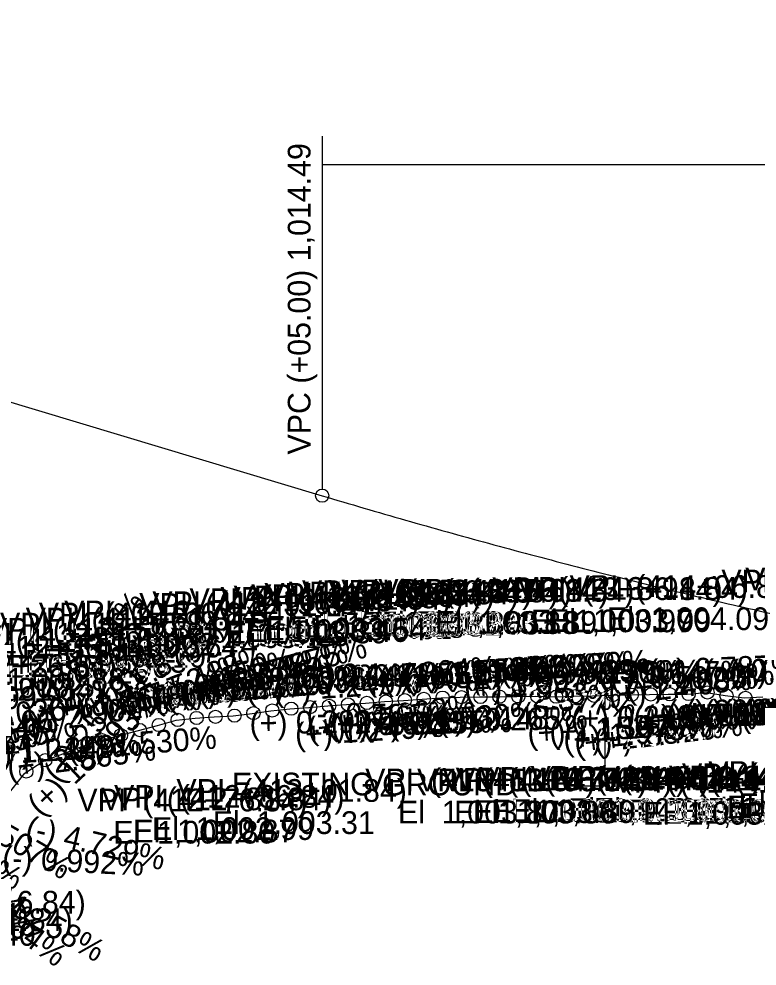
# Model space of a CAD drawing. Extents: x 150 to 16976893, y 3102 to 12559827.
# Drawn here: x 16975617.8 to 16975812.8, y 12558887.5 to 12559137.8 of the extents above; entities that cross this region are included whole.
import ezdxf

# ---------------------------------------------------------------- set-up
doc = ezdxf.new("R2010")
doc.units = 0
for name, color, linetype in [('RD_DDB_Ex_Tx', 7, 'Continuous'), ('RD_DDB_GradeTX', 7, 'Continuous'), ('RD_DDB_PI', 7, 'Continuous'), ('RD_DDB_Profile_EX', 7, 'Continuous'), ('RD_HC_TX_Sta20', 7, 'Continuous'), ('RD_XS_Misc_Line', 7, 'Continuous')]:
    doc.layers.add(name, color=color, linetype=linetype)

msp = doc.modelspace()

# ---------------------------------------------------------------- linework, layer by layer
at = {"layer": 'RD_DDB_Ex_Tx'}
for p, q in [((16975772.67, 12558935.06), (16975772.67, 12558958.98)), ((16975762.95, 12558935.06), (16975772.67, 12558935.06))]:
    msp.add_line(p, q, dxfattribs=at)
at = {"layer": 'RD_DDB_PI'}
for centre in [(16975729.74, 12558958.39), (16975734.74, 12558958.51), (16975739.74, 12558958.58), (16975744.74, 12558958.65), (16975749.74, 12558958.73), (16975754.74, 12558958.76), (16975759.74, 12558958.64), (16975764.74, 12558958.76), (16975769.74, 12558958.9), (16975774.74, 12558959.04), (16975779.74, 12558959.18), (16975784.74, 12558959.25), (16975789.74, 12558959.29), (16975794.74, 12558959.35), (16975799.74, 12558959.75), (16975804.74, 12558958.91), (16975699.74, 12558956.24), (16975704.74, 12558956.62), (16975709.74, 12558957), (16975714.74, 12558957.37), (16975719.74, 12558957.71), (16975724.74, 12558958.05), (16975809.74, 12558958.32), (16975674.74, 12558953.64), (16975679.74, 12558954.28), (16975684.74, 12558955.01), (16975689.74, 12558955.47), (16975694.74, 12558955.86), (16975654.74, 12558951.16), (16975659.74, 12558952.51), (16975664.74, 12558953.02), (16975669.74, 12558953.33), (16975644.74, 12558948.48), (16975649.74, 12558949.82), (16975639.74, 12558947.13), (16975629.74, 12558943.72), (16975634.74, 12558945.59), (16975624.74, 12558941.84), (16975619.74, 12558938.87)]:
    msp.add_circle(centre, 1.75, dxfattribs=at)
at = {"layer": 'RD_DDB_Profile_EX'}
for points in [[(16975614.37, 12558932.13), (16975619.37, 12558938.41), (16975624.37, 12558941.7), (16975629.37, 12558943.58), (16975634.37, 12558945.45), (16975639.37, 12558947.03), (16975644.37, 12558948.38), (16975649.37, 12558949.72), (16975654.37, 12558951.06), (16975659.37, 12558952.41), (16975664.37, 12558952.99), (16975669.37, 12558953.3), (16975674.37, 12558953.62), (16975679.37, 12558954.23), (16975684.37, 12558954.95), (16975689.37, 12558955.44), (16975694.37, 12558955.83), (16975699.37, 12558956.21), (16975704.37, 12558956.59), (16975709.37, 12558956.97), (16975714.37, 12558957.34), (16975719.37, 12558957.68), (16975724.37, 12558958.03), (16975729.37, 12558958.37), (16975734.37, 12558958.5), (16975739.37, 12558958.58), (16975744.37, 12558958.65), (16975749.37, 12558958.72), (16975754.37, 12558958.79), (16975759.37, 12558958.63)], [(16975759.37, 12558958.63), (16975764.37, 12558958.76), (16975769.37, 12558958.89), (16975774.37, 12558959.03), (16975779.37, 12558959.17), (16975784.37, 12558959.25), (16975789.37, 12558959.28), (16975794.37, 12558959.32), (16975799.37, 12558959.72), (16975804.37, 12558958.98), (16975809.37, 12558958.3), (16975814.37, 12558958.58)]]:
    msp.add_lwpolyline(points, dxfattribs=at)
at = {"layer": 'RD_HC_TX_Sta20'}
for p, q in [((16975697.9, 12559106.77), (16975697.9, 12559013.52)), ((16975697.9, 12559099.27), (16976247.9, 12559099.27))]:
    msp.add_line(p, q, dxfattribs=at)
msp.add_circle((16975697.9, 12559011.77), 1.75, dxfattribs=at)
at = {"layer": 'RD_XS_Misc_Line'}
msp.add_line((16975277.9, 12559137.77), (16975697.9, 12559011.77), dxfattribs=at)
msp.add_spline([(16975697.9, 12559011.77), (16975708.9, 12559008.5), (16975719.9, 12559005.32), (16975730.9, 12559002.21), (16975741.9, 12558999.18), (16975752.9, 12558996.22), (16975763.9, 12558993.34), (16975774.9, 12558990.54), (16975785.9, 12558987.81), (16975796.9, 12558985.16), (16975807.9, 12558982.59), (16975818.9, 12558980.09), (16975829.9, 12558977.67), (16975840.9, 12558975.33), (16975851.9, 12558973.06), (16975862.9, 12558970.87), (16975873.9, 12558968.76), (16975884.9, 12558966.72), (16975895.9, 12558964.76), (16975906.9, 12558962.87), (16975917.9, 12558961.06), (16975928.9, 12558959.33), (16975939.9, 12558957.67), (16975950.9, 12558956.09), (16975961.9, 12558954.59), (16975972.9, 12558953.17), (16975983.9, 12558951.82), (16975994.9, 12558950.54), (16976005.9, 12558949.35), (16976016.9, 12558948.23), (16976027.9, 12558947.18), (16976038.9, 12558946.21), (16976049.9, 12558945.32), (16976060.9, 12558944.51), (16976071.9, 12558943.77), (16976082.9, 12558943.11), (16976093.9, 12558942.52), (16976104.9, 12558942.02), (16976115.9, 12558941.58), (16976126.9, 12558941.23), (16976137.9, 12558940.95), (16976148.9, 12558940.75), (16976159.9, 12558940.62), (16976170.9, 12558940.57), (16976181.9, 12558940.6), (16976192.9, 12558940.7), (16976203.9, 12558940.88), (16976214.9, 12558941.14), (16976225.9, 12558941.47), (16976236.9, 12558941.88), (16976247.9, 12558942.36)], degree=3, dxfattribs=at)

# ---------------------------------------------------------------- texts
at = {"layer": 'RD_DDB_Ex_Tx'}
msp.add_text('EXISTING GROUND', height=6, dxfattribs=at).set_placement((16975674.08, 12558932.56))
at = {"layer": 'RD_DDB_GradeTX'}
for s, rotation, p in [('(+) 25.101%', 51.4525, (16975624.12, 12558949.19)), ('(+) 11.870%', 30.6881, (16975634.95, 12558951.39)), ('(+) 5.375%', 15.0437, (16975667.08, 12558957.59)), ('(+) 5.375%', 15.0437, (16975672.08, 12558958.93)), ('(+) 25.101%', 51.4525, (16975628.51, 12558935.43)), ('(+) 7.524%', 20.6166, (16975641.52, 12558951.36)), ('(+) 7.488%', 20.5259, (16975646.87, 12558953.34)), ('(+) 6.150%', 17.092, (16975653.6, 12558954.53)), ('(+) 5.375%', 15.0437, (16975657.08, 12558954.9)), ('(+) 5.375%', 15.0437, (16975662.08, 12558956.24)), ('(+) 1.450%', 4.1457, (16975730.12, 12558961.49)), ('(+) 1.370%', 3.9181, (16975735.14, 12558961.77)), ('(+) 1.370%', 3.9181, (16975740.14, 12558962.11)), ('(+) 1.370%', 3.9181, (16975745.14, 12558962.45)), ('(+) 0.147%', 0.4204, (16975690.78, 12558961.29)), ('(+) 1.864%', 5.3242, (16975705.26, 12558959.93)), ('(+) 1.530%', 4.3757, (16975709.69, 12558960.01)), ('(+) 0.274%', 0.7847, (16975718.88, 12558961.35)), ('(+) 1.530%', 4.3757, (16975719.69, 12558960.77)), ('(+) 1.530%', 4.3757, (16975724.69, 12558961.16)), ('(+) 0.463%', 1.3272, (16975748.6, 12558961.83)), ('(+) 0.290%', 0.8315, (16975753.57, 12558961.78)), ('(+) 0.290%', 0.8315, (16975758.57, 12558961.86)), ('(+) 0.147%', 0.4204, (16975770.78, 12558961.88)), ('(+) 2.093%', 5.9736, (16975778.37, 12558957.81)), ('(+) 0.787%', 2.2534, (16975784.26, 12558962.36)), ('(+) 0.274%', 0.7847, (16975798.87, 12558962.44)), ('(+) 0.148%', 0.4231, (16975805.49, 12558962.4)), ('(+) 1.370%', 3.9181, (16975660.34, 12558956.65)), ('(+) 1.370%', 3.9181, (16975665.34, 12558956.99)), ('(+) 0.463%', 1.3272, (16975668.63, 12558959.98)), ('(+) 0.290%', 0.8315, (16975673.58, 12558960.62)), ('(+) 2.036%', 5.813, (16975677.92, 12558957.37)), ('(+) 0.290%', 0.8317, (16975683.58, 12558960.77)), ('(+) 1.249%', 3.5746, (16975685.16, 12558957.3)), ('(+) 0.577%', 1.6513, (16975714.15, 12558960.29)), ('(+) 1.597%', 4.5659, (16975735.65, 12558957.64)), ('(-) 3.363%', 350.4538, (16975737.4, 12558961.11)), ('(+) 2.468%', 7.0355, (16975773.87, 12558956.11)), ('(-) 0.507%', 358.5486, (16975773.98, 12558961.28)), ('(+) 1.530%', 4.3757, (16975634.94, 12558954.29)), ('(+) 1.530%', 4.3757, (16975639.94, 12558954.67)), ('(+) 1.530%', 4.3757, (16975644.94, 12558955.05)), ('(+) 1.450%', 4.1457, (16975650.34, 12558955.71)), ('(+) 1.370%', 3.9181, (16975655.34, 12558956.3)), ('(-) 2.377%', 353.2234, (16975743.2, 12558957.16)), ('(+) 18.593%', 42.912, (16975623.48, 12558926.81)), ('(+) 1.864%', 5.3242, (16975625.63, 12558952.51)), ('(+) 2.036%', 5.813, (16975598.36, 12558949.27)), ('(+) 2.902%', 8.255, (16975618.64, 12558948.45)), ('(+) 2.565%', 7.3071, (16975694.38, 12558947.08)), ('(+) 2.902%', 8.255, (16975699.48, 12558948.05)), ('(+) 0.460%', 1.317, (16975789.2, 12558951.54)), ('(+) 0.482%', 1.3806, (16975793.86, 12558951.58)), ('(+) 0.577%', 1.6513, (16975794.46, 12558950.6)), ('(+) 0.504%', 1.4441, (16975798.99, 12558951.64)), ('(+) 0.526%', 1.5076, (16975803.76, 12558951.69)), ('(+) 0.549%', 1.5711, (16975809.13, 12558951.76)), ('(+) 0.290%', 0.8315, (16975678.76, 12558948.7)), ('(-) 0.507%', 358.5486, (16975693.71, 12558951.31)), ('(+) 0.533%', 1.5279, (16975703.29, 12558948.12)), ('(+) 0.555%', 1.5897, (16975708.66, 12558948.2)), ('(+) 1.530%', 4.3757, (16975715.61, 12558948.43)), ('(+) 0.148%', 0.4231, (16975725.58, 12558949.81)), ('(+) 0.265%', 0.7579, (16975728.63, 12558949.48)), ('(+) 0.290%', 0.8317, (16975763.75, 12558949.93)), ('(+) 0.512%', 1.4662, (16975780.26, 12558950.16)), ('(+) 0.533%', 1.5279, (16975783.26, 12558950.26)), ('(+) 0.555%', 1.5897, (16975788.63, 12558950.42)), ('(+) 0.265%', 0.7579, (16975808.62, 12558950.54)), ('(+) 5.375%', 15.0437, (16975594.99, 12558938.21)), ('(+) 1.249%', 3.5746, (16975690.91, 12558945.63)), ('(+) 0.512%', 1.4662, (16975700.29, 12558948.11)), ('(+) 1.152%', 3.2961, (16975752.31, 12558945.99)), ('(+) 1.197%', 3.424, (16975758.11, 12558946.2)), ('(+) 1.975%', 5.6385, (16975761.88, 12558944.15)), ('(+) 2.384%', 6.7979, (16975764.86, 12558943.2)), ('(+) 2.426%', 6.9169, (16975770.07, 12558943.69)), ('(+) 5.375%', 15.0437, (16975584.99, 12558935.52)), ('(+) 5.375%', 15.0437, (16975589.99, 12558936.87)), ('(+) 1.530%', 4.3757, (16975630.85, 12558941.94)), ('(+) 1.249%', 3.5746, (16975606.08, 12558940.33)), ('(+) 1.249%', 3.5746, (16975611.08, 12558940.65)), ('(+) 2.565%', 7.3071, (16975615.07, 12558936.91)), ('(-) 11.507%', 330.0851, (16975593.01, 12558930.99)), ('(-) 9.807%', 333.8798, (16975583.21, 12558923.87)), ('(-) 22.304%', 311.8832, (16975592.13, 12558925.84)), ('(-) 4.729%', 346.6963, (16975619.21, 12558921.34)), ('(-) 0.992%', 357.1603, (16975613.27, 12558913.18)), ('(-) 14.684%', 323.7142, (16975593.82, 12558911.76)), ('(-) 11.258%', 330.6258, (16975601.73, 12558908.85))]:
    msp.add_text(s, height=6, rotation=rotation, dxfattribs=at).set_placement(p)
at = {"layer": 'RD_DDB_PI'}
for s, p in [('VPI  (414+51.84)', (16975809.69, 12558986.74)), ('VPI  (413+86.84)', (16975742.86, 12558984.18)), ('VPI  (413+91.84)', (16975749.51, 12558984.25)), ('VPI  (414+06.84)', (16975763.27, 12558984.75)), ('VPI  (414+46.84)', (16975803.39, 12558986.22)), ('VPI  (413+11.84)', (16975671.05, 12558981.62)), ('VPI  (413+16.84)', (16975674.51, 12558982)), ('VPI  (413+21.84)', (16975679.16, 12558982.37)), ('VPI  (413+26.84)', (16975682.63, 12558982.71)), ('VPI  (413+31.84)', (16975689.1, 12558983.05)), ('VPI  (413+36.84)', (16975692.57, 12558983.39)), ('VPI  (413+41.84)', (16975699.51, 12558983.51)), ('VPI  (413+46.84)', (16975702.98, 12558983.58)), ('VPI  (413+56.84)', (16975712.74, 12558983.73)), ('VPI  (413+61.84)', (16975719.51, 12558983.76)), ('VPI  (412+91.84)', (16975649.57, 12558980.01)), ('VPI  (412+96.84)', (16975653.04, 12558980.47)), ('VPI  (413+06.84)', (16975662.86, 12558981.24)), ('VPI  (412+66.84)', (16975623.04, 12558977.51)), ('VPI  (412+71.84)', (16975629.75, 12558978.02)), ('VPI  (412+56.84)', (16975612.8, 12558974.82)), ('VPI  (412+61.84)', (16975619.57, 12558976.16)), ('El  1,003.61', (16975689.41, 12558973.87)), ('El  1,003.68', (16975692.78, 12558974.21)), ('El  1,003.75', (16975697.84, 12558974.55)), ('El  1,003.82', (16975702.43, 12558974.89)), ('El  1,003.84', (16975707.75, 12558975.01)), ('El  1,003.85', (16975712.55, 12558975.08)), ('El  1,003.88', (16975722.66, 12558975.23)), ('El  1,003.89', (16975727.75, 12558975.26)), ('El  1,003.97', (16975753.05, 12558975.68)), ('El  1,003.99', (16975757.87, 12558975.75)), ('El  1,004.09', (16975773.17, 12558976.25)), ('VPI  (412+46.84)', (16975603.04, 12558972.13)), ('VPI  (412+51.84)', (16975609.34, 12558973.48)), ('El  1,003.14', (16975659.41, 12558971.51)), ('El  1,003.23', (16975662.13, 12558971.97)), ('El  1,003.39', (16975672.46, 12558972.74)), ('El  1,003.46', (16975677.87, 12558973.12)), ('El  1,003.54', (16975682.64, 12558973.5)), ('VPI  (412+41.84)', (16975599.57, 12558970.59)), ('El  1,002.64', (16975632.93, 12558969.01)), ('El  1,002.74', (16975638.11, 12558969.52)), ('VPI  (412+31.84)', (16975589.16, 12558966.84)), ('VPI  (412+36.84)', (16975592.63, 12558968.72)), ('El  1,002.10', (16975624.35, 12558966.32)), ('El  1,002.37', (16975627.69, 12558967.66)), ('VPI  (412+26.84)', (16975582.68, 12558963.87)), ('El  1,001.83', (16975619.32, 12558964.98)), ('El  1,001.26', (16975609.47, 12558962.09)), ('El  1,001.56', (16975614.58, 12558963.63)), ('El  1,000.88', (16975602.96, 12558960.22)), ('VPI  (412+21.84)', (16975579.22, 12558957.6)), ('El  1,000.51', (16975599.47, 12558958.34)), ('El  999.91', (16975597.54, 12558955.37)), ('El  998.66', (16975590.88, 12558949.1)), ('VPI  (412+06.84)', (16975562.92, 12558947.86)), ('VPI  (413+76.84)', (16975733.16, 12558933.9)), ('VPI  (413+81.84)', (16975739.4, 12558934.04)), ('VPI  (413+96.84)', (16975752.98, 12558934.29)), ('VPI  (414+01.84)', (16975759.81, 12558934.35)), ('VPI  (414+11.84)', (16975771.46, 12558933.91)), ('VPI  (414+26.84)', (16975783.04, 12558933.9)), ('VPI  (414+31.84)', (16975789.51, 12558934.4)), ('VPI  (414+36.84)', (16975792.98, 12558934.99)), ('VPI  (414+41.84)', (16975799.93, 12558935.6)), ('VPI  (413+51.84)', (16975709.28, 12558933.65)), ('VPI  (413+66.84)', (16975722.98, 12558933.64)), ('VPI  (413+71.84)', (16975729.69, 12558933.76)), ('VPI  (414+16.84)', (16975774.93, 12558933.32)), ('VPI  (414+21.84)', (16975779.57, 12558933.6)), ('VPI  (412+86.84)', (16975642.92, 12558929.28)), ('VPI  (413+01.84)', (16975659.4, 12558930.86)), ('VPI  (412+76.84)', (16975633.22, 12558928.33)), ('VPI  (412+81.84)', (16975639.46, 12558928.64)), ('El  1,004.14', (16975804.82, 12558926.49)), ('El  1,004.26', (16975807.93, 12558927.1)), ('El  1,003.87', (16975717.93, 12558925.15)), ('El  1,003.86', (16975732.75, 12558925.14)), ('El  1,003.89', (16975737.75, 12558925.26)), ('El  1,003.92', (16975742.55, 12558925.4)), ('El  1,003.94', (16975747.87, 12558925.54)), ('El  1,003.99', (16975762.87, 12558925.79)), ('El  1,004.01', (16975769.7, 12558925.85)), ('El  1,003.92', (16975777.55, 12558925.41)), ('El  1,003.80', (16975782.64, 12558924.82)), ('El  1,003.86', (16975787.75, 12558925.1)), ('El  1,003.92', (16975792.55, 12558925.4)), ('El  1,004.02', (16975797.84, 12558925.9)), ('El  1,003.31', (16975668.99, 12558922.36)), ('El  1,002.80', (16975642.69, 12558919.83)), ('El  1,002.87', (16975647.99, 12558920.14)), ('El  1,002.99', (16975652.93, 12558920.78)), ('VPI  (412+16.84)', (16975574.57, 12558901.32)), ('VPI  (412+01.84)', (16975559.46, 12558898.11)), ('VPI  (412+11.84)', (16975571.11, 12558896.68)), ('El  997.40', (16975586.06, 12558892.82))]:
    msp.add_text(s, height=6, dxfattribs=at).set_placement(p)
at = {"layer": 'RD_HC_TX_Sta20'}
msp.add_text('VPC (+05.00) 1,014.49', height=6, rotation=90, dxfattribs=at).set_placement((16975694.83, 12559022.65))

doc.saveas('drawing.dxf')
